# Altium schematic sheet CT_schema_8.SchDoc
size 423 x 414 mm
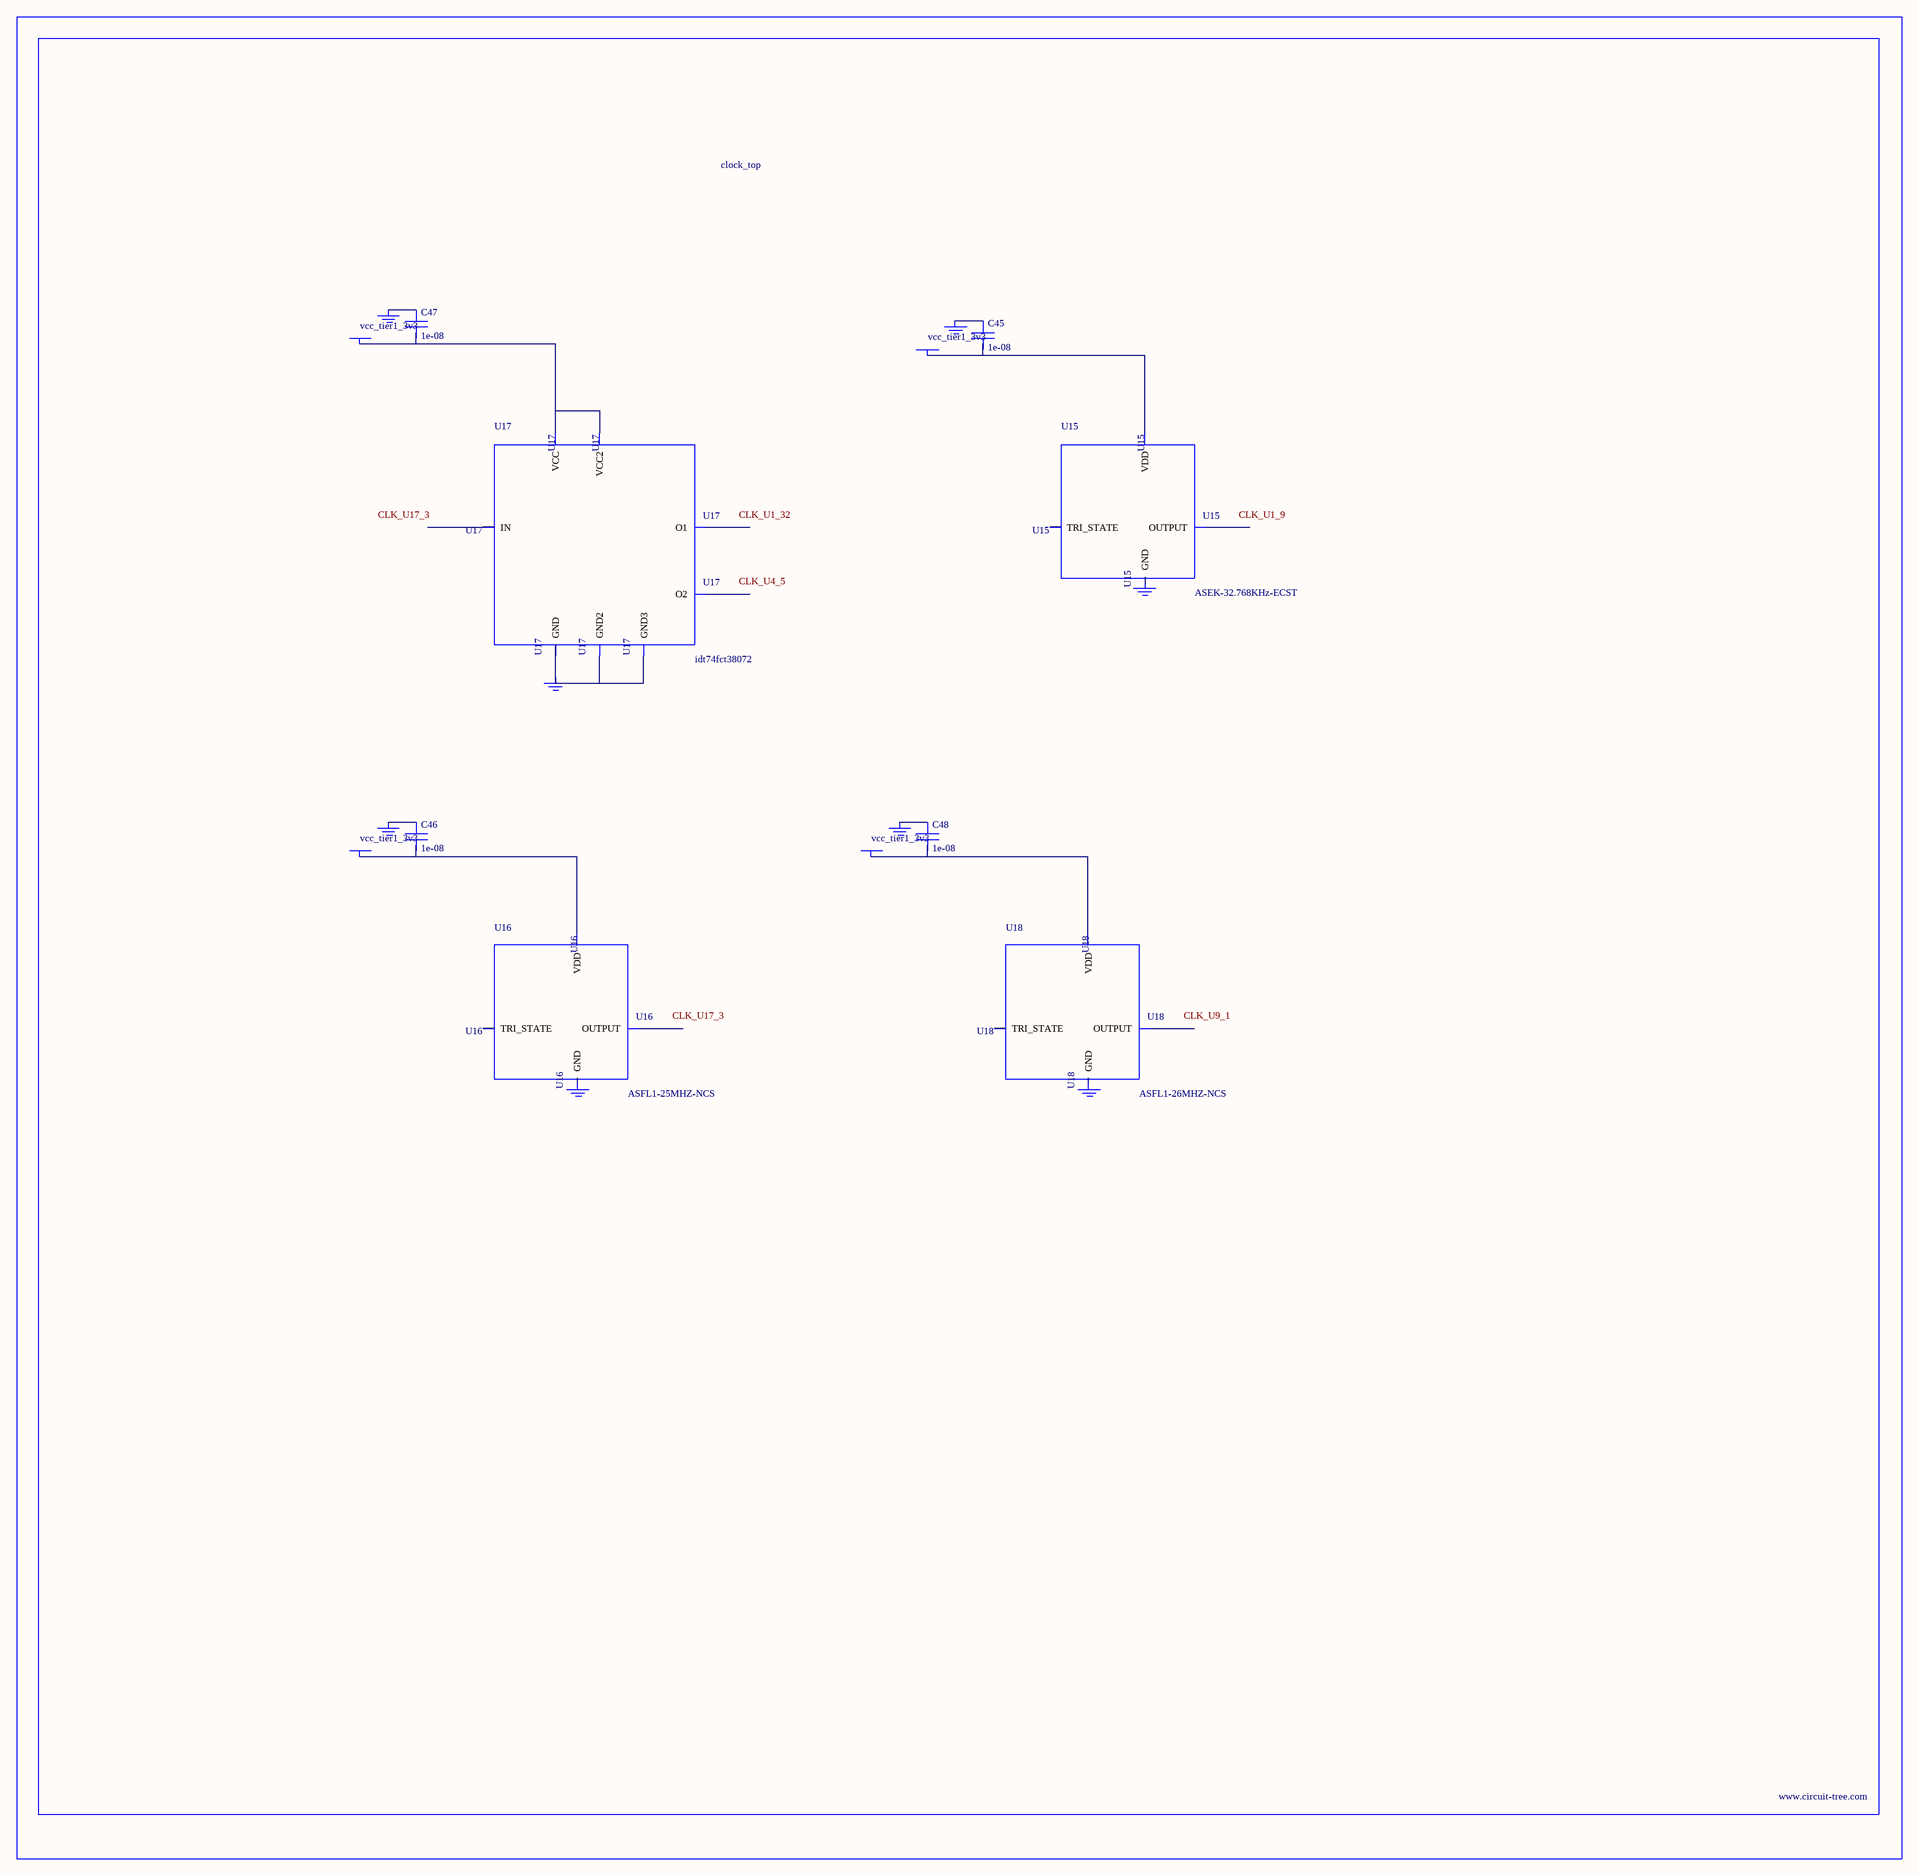
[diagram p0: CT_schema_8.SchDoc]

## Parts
BORDER7  (no value)
C45  1e-08  [C0402]
C46  1e-08  [C0402]
C47  1e-08  [C0402]
C48  1e-08  [C0402]
GND_INSTANCE_7_0  (no value)
GND_INSTANCE_7_1  (no value)
GND_INSTANCE_7_2  (no value)
GND_INSTANCE_7_3  (no value)
GND_INSTANCE_7_4  (no value)
GND_INSTANCE_7_5  (no value)
GND_INSTANCE_7_6  (no value)
GND_INSTANCE_7_7  (no value)
POWER_INSTANCE_7_0  vcc_tier1_3v3
POWER_INSTANCE_7_1  vcc_tier1_3v3
POWER_INSTANCE_7_2  vcc_tier1_3v3
POWER_INSTANCE_7_3  vcc_tier1_3v3
U15  ASEK-32.768KHz-ECST  [ASEK]
U16  ASFL1-25MHZ-NCS  [ASFL1]
U17  idt74fct38072  [IDT74FCT38072]
U18  ASFL1-26MHZ-NCS  [ASFL1]

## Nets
NetC45_1: C45.1 GND_INSTANCE_7_0.0(GND)
NetC45_2: C45.2 POWER_INSTANCE_7_0.0(PWR) U15.4(VDD)
NetC46_1: C46.1 GND_INSTANCE_7_2.0(GND)
NetC46_2: C46.2 POWER_INSTANCE_7_1.0(PWR) U16.4(VDD)
NetC47_1: C47.1 GND_INSTANCE_7_4.0(GND)
NetC47_2: C47.2 POWER_INSTANCE_7_2.0(PWR) U17.1(VCC) U17.2(VCC2)
NetC48_1: C48.1 GND_INSTANCE_7_6.0(GND)
NetC48_2: C48.2 POWER_INSTANCE_7_3.0(PWR) U18.4(VDD)
NetGND_INSTANCE_7_5_0: GND_INSTANCE_7_5.0(GND) U17.4(GND) U17.5(GND2) U17.8(GND3)

Not connected (* = marked no-connect by the designer): GND_INSTANCE_7_1 0(GND); GND_INSTANCE_7_3 0(GND); GND_INSTANCE_7_7 0(GND); U15 1(TRI_STATE) 2(GND) 3(OUTPUT); U16 1(TRI_STATE) 2(GND) 3(OUTPUT); U17 3(IN) 6(O2) 7(O1); U18 1(TRI_STATE) 2(GND) 3(OUTPUT)

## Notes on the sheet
- Labels drawn without touching a wire or pin: CLK_U1_9, CLK_U1_32, CLK_U4_5, CLK_U9_1, CLK_U17_3

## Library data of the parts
BORDER7 = BORDER_PAGE7
C45-C48 = C0402C103K3RAC
GND_INSTANCE_7_0-GND_INSTANCE_7_7 = GND
POWER_INSTANCE_7_0-POWER_INSTANCE_7_3 = PWR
